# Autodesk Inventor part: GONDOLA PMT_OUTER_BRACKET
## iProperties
Shininess: 64.0
Length Units: 11272
Angle Units: 11279
Time Units: 11290
Mass Units: 11286
Length Display Precision: 3
Angle Display Precision: 2
Compacted: True
Part Number: GONDOLA PMT_OUTER_BRACKET
Document SubType Name: Modeling
Created: 2004-08
Designer: John Blackburn
Manufacturer: Standard
Standards Organization: Custom
Material: PVC-Piping
Density: 0.0
Volumn: 0.0
Area: 0.0
PropertySet Name: Model Information
Control State: 0
Master: False
Checked Out: False
Author: John Blackburn
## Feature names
1. Base1
